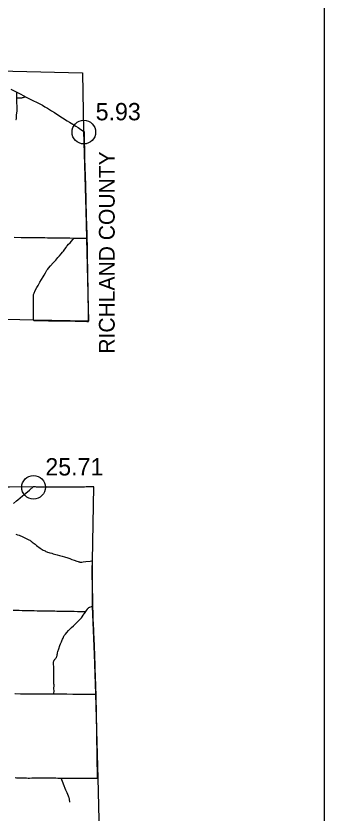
# Model space of a CAD drawing. Extents: x 1813937 to 1948437, y 826606 to 1022856.
# Drawn here: x 1928879 to 1948437, y 939932 to 990571 of the extents above; entities that cross this region are included whole.
import ezdxf

# ---------------------------------------------------------------- set-up
doc = ezdxf.new("R2010")
doc.units = 0
for name, color, linetype in [('Default', 7, 'Continuous'), ('GM_X_Adjacent_County_Text', 7, 'Continuous'), ('GM_X_County', 7, 'Continuous'), ('GM_X_County_Road', 7, 'Continuous'), ('GM_X_State_Route', 7, 'Continuous'), ('GM_X_Township', 7, 'Continuous'), ('GM_X_Township_Road', 7, 'Continuous'), ('GM_X_US_Route', 7, 'Continuous'), ('SC_Scratch1', 7, 'Continuous')]:
    doc.layers.add(name, color=color, linetype=linetype)

msp = doc.modelspace()

# ---------------------------------------------------------------- linework, layer by layer
at = {"layer": 'Default'}
for centre in [(1933189, 983191), (1929996, 960628)]:
    msp.add_circle(centre, 750, dxfattribs=at)
at = {"layer": 'GM_X_County'}
for points in [[(1925127, 987155), (1933106, 986948), (1933172, 983252), (1933307, 978234), (1933364, 976428), (1933485, 971181), (1929986, 971246), (1928265, 971283)], [(1928467, 960653), (1930020, 960674), (1933801, 960656), (1933723, 955963), (1933713, 955812), (1933717, 954747), (1933720, 953054), (1933836, 950026), (1933939, 947488), (1934048, 942901), (1934067, 942157), (1934195, 936859)]]:
    msp.add_lwpolyline(points, dxfattribs=at)
at = {"layer": 'GM_X_County_Road'}
for points in [[(1928766, 976511), (1929209, 976506), (1929390, 976503), (1929586, 976500), (1929734, 976498), (1929979, 976494), (1930209, 976490), (1930356, 976489), (1930553, 976487), (1930635, 976486), (1930717, 976486), (1930880, 976484), (1930995, 976482), (1931126, 976481), (1931257, 976479), (1931388, 976477), (1931585, 976474), (1931781, 976470), (1931896, 976468), (1932109, 976467), (1932306, 976465), (1932519, 976459), (1932572, 976457)], [(1932572, 976457), (1932733, 976453), (1932896, 976449), (1933044, 976447), (1933175, 976446), (1933290, 976445), (1933388, 976443), (1933406, 976443)], [(1928867, 957641), (1928977, 957610), (1929086, 957576), (1929164, 957548), (1929240, 957518), (1929314, 957485), (1929447, 957419), (1929579, 957351), (1929695, 957293), (1929753, 957262), (1929794, 957236), (1929848, 957199), (1929914, 957150), (1929977, 957099), (1930091, 957004), (1930180, 956934), (1930258, 956875), (1930338, 956817), (1930422, 956763), (1930616, 956641), (1930669, 956609), (1930726, 956580), (1930786, 956551), (1930831, 956531), (1930892, 956508), (1930957, 956487), (1931039, 956462), (1931147, 956434), (1931241, 956406), (1931490, 956337), (1931648, 956294), (1931820, 956242), (1931960, 956201), (1932164, 956137), (1932297, 956094), (1932431, 956048), (1932569, 955999), (1932753, 955931), (1932826, 955906), (1932879, 955890), (1932906, 955883), (1932929, 955879), (1932963, 955875), (1933010, 955872), (1933061, 955874), (1933143, 955882), (1933320, 955904), (1933583, 955936), (1933676, 955947), (1933733, 955951)], [(1928814, 947518), (1928833, 947518), (1929178, 947515), (1929325, 947513), (1929424, 947512), (1929555, 947510), (1929653, 947510), (1929801, 947509), (1930080, 947506), (1930309, 947506), (1930555, 947507), (1930654, 947508), (1930851, 947509), (1931047, 947507), (1931244, 947506), (1931286, 947506)], [(1931286, 947506), (1931425, 947505), (1931704, 947502), (1931981, 947499), (1932112, 947499), (1932489, 947494), (1932882, 947492), (1933112, 947489), (1933341, 947490), (1933587, 947488), (1933882, 947482), (1933932, 947480), (1933967, 947479)]]:
    msp.add_lwpolyline(points, dxfattribs=at)
at = {"layer": 'GM_X_State_Route'}
msp.add_lwpolyline([(1928557, 985912), (1928931, 985721), (1929141, 985613), (1929375, 985494), (1929480, 985441), (1929580, 985391), (1929917, 985221), (1930268, 985044), (1930560, 984894), (1930718, 984806), (1930887, 984705), (1931137, 984548), (1931317, 984434), (1931663, 984213), (1931829, 984108), (1932133, 983915), (1932272, 983828), (1932480, 983696), (1932687, 983563), (1932825, 983475), (1933005, 983361), (1933231, 983217)], dxfattribs=at)
at = {"layer": 'GM_X_Township'}
msp.add_lwpolyline([(1915744, 960672), (1920541, 960662), (1921738, 960652), (1922124, 960663), (1922164, 960668), (1922719, 960651), (1923180, 960652), (1925154, 960663), (1925224, 960656), (1928467, 960653), (1930020, 960674), (1933801, 960656)], dxfattribs=at)
at = {"layer": 'GM_X_Township_Road'}
for points in [[(1928931, 985368), (1928929, 985524), (1928930, 985702), (1928931, 985721)], [(1928931, 985368), (1929018, 985367), (1929072, 985366), (1929119, 985366), (1929169, 985368), (1929218, 985370), (1929254, 985374), (1929297, 985384), (1929345, 985397), (1929462, 985435), (1929480, 985441)], [(1928876, 983982), (1928887, 983994), (1928896, 984008), (1928902, 984023), (1928905, 984039), (1928907, 984055), (1928907, 984104), (1928906, 984187), (1928907, 984236), (1928911, 984285), (1928917, 984334), (1928925, 984382), (1928932, 984414), (1928944, 984462), (1928952, 984493), (1928958, 984525), (1928963, 984574), (1928964, 984640), (1928963, 984706), (1928953, 984886), (1928944, 985017), (1928936, 985164), (1928935, 985214), (1928931, 985368)], [(1933347, 978263), (1933347, 978285), (1933346, 978384), (1933343, 978597), (1933337, 978827), (1933334, 978925), (1933331, 979105), (1933327, 979269), (1933323, 979367), (1933319, 979465), (1933317, 979562), (1933315, 979644), (1933314, 979759), (1933312, 979874), (1933310, 979989), (1933309, 980038), (1933303, 980185), (1933299, 980250), (1933297, 980300), (1933295, 980365), (1933288, 980578), (1933282, 980774), (1933278, 980905), (1933274, 981020), (1933269, 981151), (1933262, 981332), (1933259, 981446), (1933255, 981561), (1933250, 981743), (1933247, 981857), (1933244, 981953), (1933243, 982068), (1933241, 982215), (1933240, 982476), (1933238, 982590), (1933236, 982745), (1933234, 982894), (1933231, 983217)], [(1933406, 976443), (1933406, 976483), (1933401, 976614), (1933399, 976680), (1933398, 976745), (1933395, 976860), (1933388, 977089), (1933380, 977285), (1933373, 977465), (1933366, 977646), (1933359, 977875), (1933349, 978154), (1933347, 978263)], [(1929994, 971238), (1929996, 971266), (1930001, 971325), (1930003, 971407), (1930002, 971538), (1929998, 971735), (1929996, 971882), (1929993, 972079), (1929992, 972227), (1929989, 972407), (1929988, 972604), (1929985, 972735), (1929986, 972784), (1929989, 972816), (1929998, 972865), (1930010, 972913), (1930025, 972959), (1930050, 973020), (1930072, 973064), (1930109, 973135), (1930215, 973322), (1930289, 973450), (1930404, 973649), (1930503, 973819), (1930599, 973990), (1930663, 974105), (1930753, 974261), (1930804, 974345), (1930849, 974414), (1930897, 974481), (1930948, 974545), (1931074, 974696), (1931247, 974893), (1931400, 975064), (1931541, 975224), (1931639, 975334), (1931747, 975458), (1931840, 975572), (1931891, 975637), (1931979, 975755), (1932056, 975861), (1932095, 975914), (1932137, 975964), (1932224, 976063), (1932311, 976159), (1932411, 976268), (1932497, 976367), (1932539, 976417), (1932572, 976457)], [(1933493, 971169), (1933492, 971204), (1933485, 971576), (1933477, 972069), (1933468, 972594), (1933465, 972758), (1933462, 972939), (1933458, 973217), (1933456, 973349), (1933455, 973529), (1933451, 973726), (1933448, 973841), (1933445, 974087), (1933440, 974317), (1933436, 974662), (1933431, 974973), (1933426, 975203), (1933423, 975334), (1933422, 975482), (1933419, 975613), (1933411, 976073), (1933409, 976303), (1933406, 976434), (1933406, 976443)], [(1929994, 971238), (1930021, 971231), (1930047, 971227), (1930080, 971224), (1930129, 971221), (1930243, 971219), (1930358, 971218), (1930516, 971217), (1930751, 971215), (1930946, 971212), (1931129, 971210), (1931308, 971206), (1931472, 971201), (1931636, 971197), (1931833, 971194), (1931964, 971192), (1932095, 971193), (1932259, 971195), (1932407, 971194), (1932538, 971192), (1932636, 971190), (1932751, 971187), (1932930, 971181), (1932996, 971180), (1933242, 971174), (1933389, 971170), (1933452, 971169), (1933493, 971169)], [(1930001, 960669), (1930091, 960667), (1930156, 960663), (1930205, 960663), (1930271, 960663), (1930369, 960664), (1930419, 960665), (1930500, 960666), (1930550, 960666), (1930664, 960665), (1930713, 960665), (1930795, 960664), (1930910, 960664), (1931025, 960663), (1931123, 960662), (1931238, 960662), (1931369, 960663), (1931550, 960663), (1931648, 960664), (1931829, 960665), (1931927, 960666), (1932058, 960666), (1932124, 960665), (1932206, 960664), (1932272, 960664), (1932337, 960665), (1932452, 960665), (1932550, 960664), (1932682, 960663), (1932813, 960663), (1933059, 960665), (1933240, 960666), (1933338, 960667), (1933519, 960668), (1933683, 960667), (1933822, 960668)], [(1933760, 953098), (1933758, 953287), (1933757, 953402), (1933754, 953582), (1933754, 953664), (1933751, 953762), (1933744, 954041), (1933740, 954221), (1933734, 954451), (1933730, 954615), (1933723, 954828), (1933719, 954910), (1933717, 954972), (1933716, 955106), (1933717, 955171), (1933717, 955237), (1933721, 955434), (1933723, 955581), (1933729, 955762), (1933730, 955808)], [(1933730, 955808), (1933732, 955882), (1933733, 955951)], [(1933309, 952730), (1933356, 952799), (1933420, 952894), (1933449, 952934), (1933470, 952959), (1933482, 952970), (1933495, 952980), (1933509, 952989), (1933538, 953004), (1933568, 953017), (1933667, 953062), (1933720, 953083), (1933760, 953098)], [(1933879, 950068), (1933876, 950143), (1933869, 950324), (1933864, 950438), (1933859, 950569), (1933843, 950979), (1933824, 951438), (1933813, 951683), (1933808, 951814), (1933800, 951994), (1933791, 952190), (1933785, 952320), (1933782, 952369), (1933777, 952451), (1933774, 952566), (1933770, 952779), (1933766, 952894), (1933760, 953090), (1933760, 953098)], [(1928699, 952817), (1928945, 952814), (1929092, 952811), (1929273, 952807), (1929404, 952803), (1929846, 952797), (1930037, 952792), (1930216, 952787), (1930419, 952779), (1930534, 952779), (1930681, 952779), (1930812, 952777), (1930943, 952775), (1931091, 952773), (1931173, 952772), (1931238, 952771), (1931353, 952770), (1931467, 952767), (1931565, 952765), (1931811, 952761), (1932024, 952755), (1932204, 952754), (1932303, 952754), (1932450, 952751), (1932581, 952748), (1932777, 952747), (1933204, 952741), (1933253, 952738), (1933271, 952738), (1933309, 952730)], [(1932614, 951913), (1932730, 952024), (1932895, 952183), (1932952, 952242), (1932996, 952291), (1933038, 952341), (1933077, 952394), (1933153, 952500), (1933217, 952596), (1933291, 952704), (1933309, 952730)], [(1931286, 947506), (1931289, 947548), (1931291, 947564), (1931296, 947646), (1931297, 947712), (1931294, 947794), (1931293, 947859), (1931294, 947925), (1931295, 947974), (1931296, 948022), (1931295, 948070), (1931295, 948086), (1931295, 948102), (1931294, 948119), (1931294, 948134), (1931291, 948247), (1931290, 948295), (1931289, 948344), (1931288, 948393), (1931286, 948541), (1931280, 948869), (1931274, 949230), (1931270, 949394), (1931270, 949492), (1931273, 949541), (1931278, 949573), (1931283, 949589), (1931289, 949604), (1931295, 949619), (1931303, 949633), (1931312, 949647), (1931331, 949673), (1931352, 949698), (1931387, 949733), (1931420, 949769), (1931440, 949795), (1931448, 949809), (1931463, 949839), (1931474, 949869), (1931483, 949901), (1931492, 949949), (1931502, 950014), (1931511, 950062), (1931522, 950110), (1931545, 950189), (1931602, 950360), (1931674, 950578), (1931712, 950686), (1931731, 950731), (1931766, 950805), (1931800, 950880), (1931838, 950970), (1931871, 951045), (1931926, 951164), (1931949, 951208), (1931967, 951235), (1931986, 951262), (1932018, 951299), (1932117, 951409), (1932215, 951519), (1932259, 951567), (1932329, 951636), (1932412, 951716), (1932529, 951831), (1932599, 951899), (1932614, 951913)], [(1933967, 947479), (1933963, 947588), (1933959, 947802), (1933952, 947998), (1933941, 948228), (1933938, 948392), (1933932, 948539), (1933927, 948637), (1933921, 948768), (1933918, 948915), (1933911, 949144), (1933905, 949324), (1933898, 949537), (1933892, 949684), (1933886, 949865), (1933879, 950068)], [(1934066, 942151), (1934064, 942235), (1934056, 942413), (1934053, 942510), (1934052, 942559), (1934050, 942608), (1934049, 942641), (1934049, 942690), (1934048, 942738), (1934047, 942786), (1934046, 942849), (1934045, 942865), (1934044, 942881), (1934040, 942995), (1934039, 943044), (1934039, 943094), (1934036, 943241), (1934035, 943323), (1934030, 943504), (1934031, 943684), (1934026, 944094), (1934019, 944373), (1934016, 944521), (1934013, 944718), (1934010, 944849), (1934007, 945259), (1934003, 945571), (1934000, 945768), (1933993, 946162), (1933990, 946326), (1933985, 946588), (1933982, 946736), (1933981, 946851), (1933980, 946949), (1933975, 947212), (1933967, 947479)], [(1928819, 942182), (1928912, 942180), (1929124, 942173), (1929239, 942169), (1929402, 942164), (1929550, 942160), (1929648, 942158), (1929746, 942158), (1929893, 942160), (1930187, 942166), (1930378, 942171), (1930492, 942171), (1930594, 942168), (1930694, 942167), (1930776, 942163), (1930842, 942162), (1930940, 942164), (1930989, 942164), (1931070, 942164), (1931267, 942162), (1931414, 942160), (1931528, 942157), (1931752, 942154)], [(1931752, 942154), (1931866, 942154), (1931948, 942153), (1932096, 942152), (1932360, 942150), (1932475, 942150), (1932574, 942151), (1932688, 942152), (1932918, 942152), (1933115, 942151), (1933230, 942152), (1933345, 942152), (1933444, 942152), (1933641, 942151), (1933822, 942151), (1934066, 942151)], [(1932257, 940886), (1932252, 940906), (1932236, 940952), (1932211, 941013), (1932123, 941209), (1932047, 941391), (1932010, 941483), (1931946, 941652), (1931833, 941944), (1931752, 942154)], [(1932300, 940615), (1932293, 940681), (1932286, 940729), (1932270, 940826), (1932261, 940874), (1932257, 940886)]]:
    msp.add_lwpolyline(points, dxfattribs=at)
at = {"layer": 'GM_X_US_Route'}
msp.add_lwpolyline([(1928728, 959598), (1928911, 959763), (1928998, 959837), (1929288, 960078), (1929504, 960254), (1929732, 960443), (1930001, 960669)], dxfattribs=at)
at = {"layer": 'SC_Scratch1'}
msp.add_lwpolyline([(1813937, 826606), (1813937, 1022856), (1948437, 1022856), (1948437, 826606)], close=True, dxfattribs=at)

# ---------------------------------------------------------------- texts
at = {"layer": 'Default'}
for s, p in [('5.93', (1933939, 983941)), ('25.71', (1930746, 961378))]:
    msp.add_text(s, height=1100, dxfattribs=at).set_placement(p)
at = {"layer": 'GM_X_Adjacent_County_Text'}
msp.add_text('RICHLAND COUNTY', height=1000, rotation=90, dxfattribs=at).set_placement((1935146, 969115))

doc.saveas('drawing.dxf')
